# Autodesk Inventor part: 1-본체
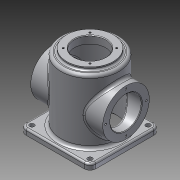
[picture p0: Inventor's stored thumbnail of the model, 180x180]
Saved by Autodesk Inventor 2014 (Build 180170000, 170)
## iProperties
Created: 2015-10
Part Number: 1-본체
Material: 알루미늄 6061
Document SubType Name: Modeling
Designer: Administrator
Density: 2.71 g/cm^3
Appearance: 알루미늄 - 평지
Mass: 986.425 g
Surface Area: 1037.85 cm^2
Volume: 363.995 cm^3
Author: Administrator
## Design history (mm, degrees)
sketch "스케치2"
  geometry: L1 (0, 62.5)-(50, 62.5); L2 (50, 62.5)-(50, -62.5); L3 (50, -62.5)-(0, -62.5); L4 (0, -62.5)-(0, 62.5); L5 (50, 62.5)-(40, 62.5); L6 (40, 62.5)-(40, 57.5); L7 (40, 57.5)-(50, 57.5); L8 (50, 57.5)-(50, 62.5); 2 further points
  constraints: 16 end point, 4 parallel, 2 horizontal, 2 perpendicular, 1 coincident, 1 midpoint
  dimensions: "d2" = 100 diameter of L2 L4; "d3" = 125 distance of L1.end L2.end; "d4" = 80 diameter of L6 L4; "d5" = 120 distance between parallel lines of L3 L7
revolve "회전1" sketch "스케치2" stored, may be unused: angle "d6" = 90 deg
sketch "스케치3"
  geometry: L1 (-60, -60)-(60, -60); L2 (60, -60)-(60, 60); L3 (60, 60)-(-60, 60); L4 (-60, 60)-(-60, -60); 3 further points
  constraints: 8 end point, 2 midpoint, 2 parallel, 2 perpendicular, 1 horizontal, 1 horizontal alignment, 1 vertical alignment
  dimensions: "d7" = 120 distance of L2.end L3.end
extrude "돌출1" join sketch "스케치3" distance "d8" = 10; taper "d9" = 0 deg
fillet "모깎기1" dims "d10" = 10
sketch "스케치4"
  geometry: L1 (50, -62.5)-(-50, -62.5) reference; C1 r 40 at (0, -2.5); 1 further point
  constraints: 1 centre point, 1 midpoint, 1 vertical alignment
  dimensions: "d11" = 80 diameter of C1; "d128" = 60 distance from line of L1 C1.centre
extrude "돌출2" join sketch "스케치4" stored distance "d12" = 124; taper "d13" = 0 deg
hole "구멍1" diameter "d16" = 90; stored, may be unused: countersink angle "d20" = 90 deg, drill point angle "d22" = 0 deg; dims "d14" = 10, "d15" = 10, "d17" = 6, "d18" = 90, "d19" = 112, "d21" = 112
hole "구멍2" diameter "d25" = 54; stored, may be unused: countersink angle "d29" = 90 deg, drill point angle "d31" = 0 deg; dims "d23" = 10, "d24" = 10, "d26" = 6, "d27" = 90, "d28" = 112, "d30" = 13
hole "구멍3" diameter "d34" = 54; stored, may be unused: countersink angle "d38" = 90 deg, drill point angle "d40" = 0 deg; dims "d32" = 10, "d33" = 10, "d35" = 6, "d36" = 90, "d37" = 112, "d39" = 13
sketch "스케치5"
  geometry: L1 (0, 0)-(-22.981, -22.981); L2 (-62, 40)-(-30, 40) reference
  constraints: 2 end point
  dimensions: "d78" = 45 deg angle of L2 L1; "d79" = 32.5 distance of L1.start L1.end
hole "구멍8" sketch "스케치5" at (-22.981, -22.981) diameter "d80" = 3.242; stored, may be unused: countersink angle "d84" = 90 deg, drill point angle "d86" = 118 deg; dims "d81" = 8, "d82" = 90, "d83" = 112, "d85" = 10
sketch "스케치6"
  geometry: L1 (-2.5, 0)-(-35, 0)
  constraints: 2 end point, 1 horizontal
  dimensions: "d90" = 32.5 distance of L1.start L1.end
hole "구멍9" sketch "스케치6" at (-35, 0) diameter "d91" = 3.242; stored, may be unused: countersink angle "d95" = 90 deg, drill point angle "d97" = 118 deg; dims "d92" = 8, "d93" = 90, "d94" = 112, "d96" = 10
sketch "스케치7"
  geometry: L1 (2.5, 0)-(35, 0)
  constraints: 2 end point, 1 horizontal
  dimensions: "d98" = 32.5 distance of L1.start L1.end
hole "구멍10" sketch "스케치7" at (35, 0) diameter "d99" = 3.242; stored, may be unused: countersink angle "d103" = 90 deg, drill point angle "d105" = 118 deg; dims "d100" = 8, "d101" = 90, "d102" = 112, "d104" = 10
node "작업 평면1"
sketch "스케치8"
  geometry: L1 (-2.204, 4.065)-(-2.204, 10.935); L2 (-2.204, 10.935)-(2.204, 10.935); L3 (2.204, 10.935)-(2.204, 4.065); L4 (2.204, 4.065)-(-2.204, 4.065); L5 (50, -62.5)-(-50, -62.5) reference; 3 further points
  constraints: 2 midpoint, 1 vertical alignment, 2 other
  dimensions: "d109" = 70 distance from line of L5 point (-2.204, 7.5)
feature "엠보싱1" sketch "스케치8" dims "d2" = 100, "d3" = 125, "d4" = 80, "d5" = 120, "d10" = 10, "d110" = 0.5, "d111" = 0
fillet "모깎기2" dims "d112" = 5
fillet "모깎기3" dims "d113" = 3
fillet "모깎기4" dims "d114" = 3
fillet "모깎기5" dims "d115" = 5
fillet "모깎기6" dims "d116" = 5
chamfer "모따기1" distance "d117" = 3; stored, may be unused: second distance "d118" = 2, angle "d119" = 45 deg
fillet "모깎기7" dims "d120" = 3
fillet "모깎기8" dims "d121" = 3
chamfer "모따기2" distance "d122" = 1; stored, may be unused: second distance "d123" = 2, angle "d124" = 45 deg
chamfer "모따기3" distance "d125" = 1; stored, may be unused: second distance "d126" = 2, angle "d127" = 45 deg
sketch "스케치9"
  geometry: L1 (50, 50)-(-50, 50); L2 (-50, 50)-(-50, -50); L3 (-50, -50)-(50, -50); L4 (50, -50)-(50, 50); 3 further points
  constraints: 8 end point, 2 midpoint, 2 parallel, 1 horizontal, 1 horizontal alignment, 1 perpendicular, 1 vertical alignment
  dimensions: "d129" = 100 distance of L3.end L1.start; "d130" = 100 distance of L2.end L3.end
hole "구멍11" sketch "스케치9" at (50, 50) diameter "d131" = 8; stored, may be unused: countersink angle "d135" = 90 deg, drill point angle "d137" = 118 deg; dims "d132" = 8, "d133" = 90, "d134" = 112, "d136" = 10
node "솔리드1"
pattern_circular "원형 패턴1" dims angle "d88" = 360 deg
pattern_circular "원형 패턴2" dims angle "d107" = 360 deg
pattern_linear "직사각형 패턴1" dims "d140" = 100 (= d129)
